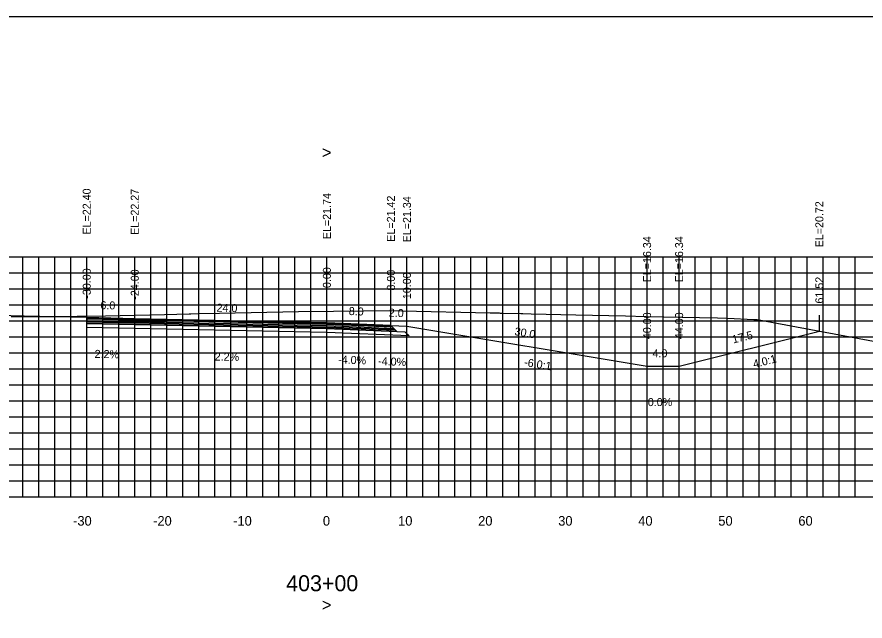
# Model space of a CAD drawing. Extents: x 1800976 to 1805104, y 250057 to 250580.
# Drawn here: x 1802252.3 to 1802358.2, y 250193.9 to 250269.4 of the extents above; entities that cross this region are included whole.
import ezdxf

# ---------------------------------------------------------------- set-up
doc = ezdxf.new("R2010")
doc.units = 0
for name, color, linetype in [('1', 7, 'Continuous'), ('10', 7, 'Continuous'), ('3', 7, 'Continuous'), ('4', 7, 'Continuous'), ('60', 7, 'Continuous'), ('BASE', 7, 'Continuous'), ('CL-CNST', 7, 'Continuous'), ('Level 62', 7, 'Continuous'), ('LOWER BINDER', 7, 'Continuous'), ('M-ROADS', 7, 'Continuous'), ('UPPER BINDER', 7, 'Continuous'), ('WEARING', 7, 'Continuous')]:
    doc.layers.add(name, color=color, linetype=linetype)

msp = doc.modelspace()

# ---------------------------------------------------------------- linework, layer by layer
for p, q in [((1802261, 250231.84), (1802261, 250233.84)), ((1802267, 250231.7), (1802267, 250233.7)), ((1802291, 250231.18), (1802291, 250233.18)), ((1802299, 250230.86), (1802299, 250232.86)), ((1802301, 250230.78), (1802301, 250232.78)), ((1802352.52, 250230.16), (1802352.52, 250232.16)), ((1802331, 250225.78), (1802331, 250227.78)), ((1802335, 250225.78), (1802335, 250227.78))]:
    msp.add_line(p, q)
msp.add_lwpolyline([(1802141, 250079.43), (1802441, 250079.43), (1802441, 250269.43), (1802141, 250269.43)], close=True)
at = {"layer": '60'}
for p, q in [((1802141, 250209.43), (1802441, 250209.43)), ((1802261, 250209.37), (1802261, 250209.43)), ((1802271, 250209.37), (1802271, 250209.43)), ((1802281, 250209.37), (1802281, 250209.43)), ((1802291, 250209.37), (1802291, 250209.43)), ((1802301, 250209.37), (1802301, 250209.43)), ((1802311, 250209.37), (1802311, 250209.43)), ((1802321, 250209.37), (1802321, 250209.43)), ((1802331, 250209.37), (1802331, 250209.43)), ((1802341, 250209.37), (1802341, 250209.43)), ((1802351, 250209.37), (1802351, 250209.43))]:
    msp.add_line(p, q, dxfattribs=at)
at = {"layer": 'BASE'}
msp.add_lwpolyline([(1802261, 250231.12), (1802267, 250230.98), (1802291, 250230.46), (1802299.75, 250230.11), (1802300.75, 250230.07), (1802301.27, 250229.55), (1802291, 250229.96), (1802267, 250230.48), (1802261, 250230.62)], close=True, dxfattribs=at)
at = {"layer": 'CL-CNST'}
for points in [[(1802161.75, 250232.24), (1802164.79, 250232.3), (1802173.84, 250232.42), (1802177.65, 250232.49), (1802185.93, 250232.61), (1802190.51, 250232.5), (1802198.02, 250232.33), (1802203.63, 250232.1), (1802208.1, 250231.91), (1802208.69, 250231.48), (1802209.36, 250231.03), (1802209.96, 250231.47), (1802210.62, 250231.95), (1802215.69, 250232.14), (1802220.7, 250232.33), (1802226.08, 250232.41), (1802232.79, 250232.54), (1802240.34, 250232.36), (1802244.88, 250232.26), (1802253.2, 250232.06), (1802261, 250231.88)], [(1802261, 250231.84), (1802267, 250231.7), (1802291, 250231.18), (1802299, 250230.86), (1802301, 250230.78), (1802331, 250225.78), (1802335, 250225.78), (1802352.52, 250230.16)]]:
    msp.add_lwpolyline(points, dxfattribs=at)
at = {"layer": 'Level 62'}
for p, q in [((1802141, 250239.43), (1802441, 250239.43)), ((1802253, 250209.43), (1802253, 250239.43)), ((1802255, 250209.43), (1802255, 250239.43)), ((1802257, 250209.43), (1802257, 250239.43)), ((1802259, 250209.43), (1802259, 250239.43)), ((1802261, 250209.43), (1802261, 250239.43)), ((1802263, 250209.43), (1802263, 250239.43)), ((1802265, 250209.43), (1802265, 250239.43)), ((1802267, 250209.43), (1802267, 250239.43)), ((1802269, 250209.43), (1802269, 250239.43)), ((1802271, 250209.43), (1802271, 250239.43)), ((1802273, 250209.43), (1802273, 250239.43)), ((1802275, 250209.43), (1802275, 250239.43)), ((1802277, 250209.43), (1802277, 250239.43)), ((1802279, 250209.43), (1802279, 250239.43)), ((1802281, 250209.43), (1802281, 250239.43)), ((1802283, 250209.43), (1802283, 250239.43)), ((1802285, 250209.43), (1802285, 250239.43)), ((1802287, 250209.43), (1802287, 250239.43)), ((1802289, 250209.43), (1802289, 250239.43)), ((1802291, 250209.43), (1802291, 250239.43)), ((1802293, 250209.43), (1802293, 250239.43)), ((1802295, 250209.43), (1802295, 250239.43)), ((1802297, 250209.43), (1802297, 250239.43)), ((1802299, 250209.43), (1802299, 250239.43)), ((1802301, 250209.43), (1802301, 250239.43)), ((1802303, 250209.43), (1802303, 250239.43)), ((1802305, 250209.43), (1802305, 250239.43)), ((1802307, 250209.43), (1802307, 250239.43)), ((1802309, 250209.43), (1802309, 250239.43)), ((1802311, 250209.43), (1802311, 250239.43)), ((1802313, 250209.43), (1802313, 250239.43)), ((1802315, 250209.43), (1802315, 250239.43)), ((1802317, 250209.43), (1802317, 250239.43)), ((1802319, 250209.43), (1802319, 250239.43)), ((1802321, 250209.43), (1802321, 250239.43)), ((1802323, 250209.43), (1802323, 250239.43)), ((1802325, 250209.43), (1802325, 250239.43)), ((1802327, 250209.43), (1802327, 250239.43)), ((1802329, 250209.43), (1802329, 250239.43)), ((1802331, 250209.43), (1802331, 250239.43)), ((1802333, 250209.43), (1802333, 250239.43)), ((1802335, 250209.43), (1802335, 250239.43)), ((1802337, 250209.43), (1802337, 250239.43)), ((1802339, 250209.43), (1802339, 250239.43)), ((1802341, 250209.43), (1802341, 250239.43)), ((1802343, 250209.43), (1802343, 250239.43)), ((1802345, 250209.43), (1802345, 250239.43)), ((1802347, 250209.43), (1802347, 250239.43)), ((1802349, 250209.43), (1802349, 250239.43)), ((1802351, 250209.43), (1802351, 250239.43)), ((1802353, 250209.43), (1802353, 250239.43)), ((1802355, 250209.43), (1802355, 250239.43)), ((1802357, 250209.43), (1802357, 250239.43)), ((1802141, 250237.43), (1802441, 250237.43)), ((1802141, 250235.43), (1802441, 250235.43)), ((1802141, 250233.43), (1802441, 250233.43)), ((1802141, 250231.43), (1802441, 250231.43)), ((1802141, 250229.43), (1802441, 250229.43)), ((1802141, 250227.43), (1802441, 250227.43)), ((1802141, 250225.43), (1802441, 250225.43)), ((1802141, 250223.43), (1802441, 250223.43)), ((1802141, 250221.43), (1802441, 250221.43)), ((1802141, 250219.43), (1802441, 250219.43)), ((1802141, 250217.43), (1802441, 250217.43)), ((1802141, 250215.43), (1802441, 250215.43)), ((1802141, 250213.43), (1802441, 250213.43)), ((1802141, 250211.43), (1802441, 250211.43)), ((1802141, 250209.43), (1802441, 250209.43))]:
    msp.add_line(p, q, dxfattribs=at)
at = {"layer": 'LOWER BINDER'}
for points in [[(1802267, 250231.36), (1802291, 250230.84), (1802299.36, 250230.5), (1802299.55, 250230.3), (1802291, 250230.65), (1802267, 250231.17), (1802261, 250231.31), (1802261, 250231.5)], [(1802267, 250231.17), (1802291, 250230.65), (1802299.55, 250230.3), (1802299.75, 250230.11), (1802291, 250230.46), (1802267, 250230.98), (1802261, 250231.12), (1802261, 250231.31)]]:
    msp.add_lwpolyline(points, close=True, dxfattribs=at)
at = {"layer": 'M-ROADS'}
msp.add_lwpolyline([(1802251.54, 250231.99), (1802252.64, 250231.96), (1802259.54, 250232), (1802259.72, 250232), (1802259.86, 250232.01), (1802263.36, 250232.07), (1802270.72, 250232.24), (1802273.8, 250232.31), (1802274, 250232.31), (1802275.04, 250232.34), (1802277.58, 250232.39), (1802287.47, 250232.59), (1802291.84, 250232.64), (1802299.36, 250232.71), (1802300.35, 250232.68), (1802311.39, 250232.43), (1802312.53, 250232.42), (1802312.64, 250232.41), (1802312.89, 250232.41), (1802315.25, 250232.37), (1802315.48, 250232.36), (1802316.5, 250232.33), (1802322.09, 250232.2), (1802328.29, 250232.06), (1802330.85, 250232), (1802339.8, 250231.81), (1802340.93, 250231.77), (1802341.05, 250231.76), (1802344.34, 250231.62), (1802344.71, 250231.6), (1802344.77, 250231.59), (1802359.28, 250228.9)], dxfattribs=at)
at = {"layer": 'UPPER BINDER'}
msp.add_lwpolyline([(1802299.36, 250230.5), (1802299.16, 250230.7), (1802291, 250231.03), (1802267, 250231.55), (1802261, 250231.69), (1802261, 250231.5), (1802267, 250231.36), (1802291, 250230.84)], close=True, dxfattribs=at)
at = {"layer": 'WEARING'}
msp.add_lwpolyline([(1802299.16, 250230.7), (1802299, 250230.86), (1802291, 250231.18), (1802267, 250231.7), (1802261, 250231.84), (1802261, 250231.69), (1802267, 250231.55), (1802291, 250231.03)], close=True, dxfattribs=at)

# ---------------------------------------------------------------- texts
for s, rotation, p in [('-6.0:1', 350.5377, (1802315.59, 250225.81)), ('4.0:1', 14.0362, (1802344.37, 250225.54))]:
    msp.add_text(s, height=1, rotation=rotation).set_placement(p)
at = {"layer": '1'}
msp.add_text('403+00', height=2, dxfattribs=at).set_placement((1802285.92, 250197.63))
at = {"layer": '10'}
for s, p in [('-30', (1802259.3, 250205.83)), ('-20', (1802269.3, 250205.83)), ('-10', (1802279.3, 250205.83)), ('0', (1802290.5, 250205.83)), ('10', (1802299.9, 250205.83)), ('20', (1802309.9, 250205.83)), ('30', (1802319.9, 250205.83)), ('40', (1802329.9, 250205.83)), ('50', (1802339.9, 250205.83)), ('60', (1802349.9, 250205.83))]:
    msp.add_text(s, height=1.2, dxfattribs=at).set_placement(p)
at = {"layer": '3'}
for s, p in [('EL=22.40', (1802261.5, 250242.23)), ('EL=22.27', (1802267.5, 250242.18)), ('EL=21.74', (1802291.5, 250241.65)), ('EL=21.42', (1802299.5, 250241.33)), ('EL=21.34', (1802301.5, 250241.25)), ('EL=20.72', (1802353.02, 250240.63)), ('EL=16.34', (1802331.5, 250236.25)), ('EL=16.34', (1802335.5, 250236.25)), ('-30.00', (1802261.5, 250234.21)), ('-24.00', (1802267.5, 250234.08)), ('0.00', (1802291.5, 250235.54)), ('8.00', (1802299.5, 250235.22)), ('10.00', (1802301.5, 250234.15)), ('61.52', (1802353.02, 250233.6)), ('40.00', (1802331.5, 250229.15)), ('44.00', (1802335.5, 250229.15))]:
    msp.add_text(s, height=1, rotation=90, dxfattribs=at).set_placement(p)
at = {"layer": '4'}
for s, rotation, p in [('6.0', 358.7397, (1802262.7, 250232.9)), ('24.0', 358.7397, (1802277.21, 250232.58)), ('8.0', 357.7094, (1802293.72, 250232.17)), ('2.0', 357.7094, (1802298.72, 250231.97)), ('30.0', 350.5377, (1802314.39, 250229.66)), ('17.5', 14.0362, (1802341.77, 250228.6)), ('2.2%', 358.7397, (1802261.98, 250226.81)), ('2.2%', 358.7397, (1802276.98, 250226.48)), ('-4.0%', 357.7094, (1802292.39, 250226.12)), ('-4.0%', 357.7094, (1802297.39, 250225.92))]:
    msp.add_text(s, height=1, rotation=rotation, dxfattribs=at).set_placement(p)
for s, p in [('4.0', (1802331.68, 250226.88)), ('0.0%', (1802331.09, 250220.78))]:
    msp.add_text(s, height=1, dxfattribs=at).set_placement(p)
at = {"layer": '60'}
for p in [(1802290.39, 250251.75), (1802290.39, 250195.18)]:
    msp.add_text('>', height=1.5, dxfattribs=at).set_placement(p)

doc.saveas('drawing.dxf')
